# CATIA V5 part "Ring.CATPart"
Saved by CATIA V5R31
Part number: Part1.1
Bounding box of the stored display mesh (mm): x -5 to 5, y -15 to 15, z -15 to 15
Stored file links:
  D:\PROJECTS\Project 2021\US EDITION\CATIA V5 6R 2021\Resources\Part Files\c12_catia_v5_6r2021_prt\c12_catia_v5-6r2021 figr_12-15\Ring.CATPart
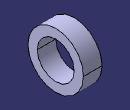
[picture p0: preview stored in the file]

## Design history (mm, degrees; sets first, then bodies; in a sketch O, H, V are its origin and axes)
Body1 (main body)
  Sketch1 on yz-plane, origin (0, 0, 0), H (0, 1, 0), V (0, 0, 1)
    circle A1 centre (0, 0) radius 15
    circle A2 centre (0, 0) radius 10
    radius A1 = 15
    radius A2 = 10
  Pad1: profile Sketch1, direction (1, 0, 0), length 5, mirrored extent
